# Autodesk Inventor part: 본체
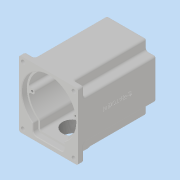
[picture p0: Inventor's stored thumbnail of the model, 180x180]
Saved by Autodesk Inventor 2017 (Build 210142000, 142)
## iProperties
Part Number: 본체
Material: 일반
Document SubType Name: Modeling
Designer: MRC
Density: 1 g/cm^3
Appearance: 기본값
Mass: 520.076 g
Surface Area: 1170.75 cm^2
Volume: 520.076 cm^3
Author: MRC
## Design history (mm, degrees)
sketch "스케치1"
  geometry: L1 (49, 55)-(-49, 55); L2 (-49, 55)-(-49, -55); L3 (-49, -55)-(49, -55); L4 (49, -55)-(49, 55); L5 (49, 55)-(-49, -55); L6 (-49, 55)-(49, -55); 1 further point
  constraints: 12 end point, 2 midpoint, 2 parallel, 1 horizontal, 1 perpendicular
  dimensions: "d0" = 98 distance of L3.end L2.end; "d1" = 110 distance of L2.end L1.end
extrude "돌출1" new body sketch "스케치1" distance "d2" = 10; taper "d3" = 0 deg
fillet "모깎기1" dims "d4" = 3
sketch "스케치2"
  geometry: L1 (46, 55)-(-46, 55) reference; L2 (33, -55)-(-33, -55); L3 (-33, -55)-(-33, 55); L4 (-33, 55)-(33, 55); L5 (33, 55)-(33, -55); L6 (33, -55)-(-33, 55); L7 (-33, -55)-(33, 55); 1 further point
  constraints: 12 end point, 2 midpoint, 2 parallel, 1 horizontal, 1 perpendicular, 1 point on line
  dimensions: "d5" = 66 distance of L3.end L4.end
extrude "돌출2" join sketch "스케치2" distance "d6" = 120; taper "d7" = 0 deg
sketch "스케치3"
  geometry: L1 (-49, -38)-(49, -38); L2 (49, -38)-(49, 28); L3 (49, 28)-(-49, 28); L4 (-49, 28)-(-49, -38); L5 (-49, -38)-(49, 28); L6 (49, -38)-(-49, 28); L7 (46, 55)-(-46, 55) reference; 3 further points
  constraints: 12 end point, 3 midpoint, 2 parallel, 1 horizontal, 1 perpendicular, 1 vertical alignment
  dimensions: "d8" = 98 distance of L3.end L2.end; "d9" = 66 distance of L2.end L1.end; "d10" = 27 distance between parallel lines of L7 L3
extrude "돌출3" join sketch "스케치3" distance "d11" = 120; taper "d12" = 0 deg
fillet "모깎기2" dims "d13" = 3
fillet "모깎기3" dims "d14" = 3
fillet "모깎기4" dims "d15" = 3
fillet "모깎기5" dims "d16" = 3
sketch "스케치4"
  geometry: L1 (-49, -41)-(-49, -52) reference; L2 (-46, -55)-(-36, -55) reference; C1 r 3.5 at (-42, -48); C2 r 3.5 at (-42, 48); C3 r 3.5 at (42, 48); C4 r 3.5 at (42, -48); 1 further point
  constraints: 4 centre point, 2 horizontal alignment, 2 vertical alignment
  dimensions: "d17" = 7 diameter of C1; "d18" = 7 diameter of C2; "d19" = 7 diameter of C3; "d20" = 7 diameter of C4; "d21" = 7 distance from line of L1 C1.centre; "d22" = 7 distance from line of L2 C1.centre; "d23" = 84 distance of C4.centre C1.centre; "d24" = 96 distance of C1.centre C2.centre
extrude "돌출4" cut sketch "스케치4" distance "d25" = 120; taper "d26" = 0 deg
sketch "스케치5"
  geometry: L1 (-27, -21)-(27, -21); L2 (27, -21)-(27, 33); L3 (27, 33)-(-27, 33); L4 (-27, 33)-(-27, -21); L5 (-27, -21)-(27, 33); L6 (27, -21)-(-27, 33); L7 (-30, -55)-(30, -55) reference; 3 further points
  constraints: 12 end point, 3 midpoint, 2 parallel, 1 horizontal, 1 perpendicular, 1 vertical alignment
  dimensions: "d27" = 54 distance of L3.end L2.end; "d28" = 54 distance of L2.end L1.end; "d29" = 61 distance from line of L7 point (0, 6)
extrude "돌출5" join sketch "스케치5" distance "d30" = 7; taper "d31" = 0 deg
fillet "모깎기6" dims "d32" = 3
fillet "모깎기7" dims "d33" = 3
sketch "스케치6"
  geometry: L1 (-46, 55)-(46, 55) reference; L2 (-23, -33.249)-(-23, -42); L3 (-20, -45)-(20, -45); L4 (23, -42)-(23, -33.249); L5 (0, 0)-(0, -65.918); A1 r 42 centre (0, 5) between (25.375, -28.468) and (-25.375, -28.468); A2 r 6 centre (29, -33.249) between (25.375, -28.468) and (23, -33.249); A3 r 6 centre (-29, -33.249) between (-23, -33.249) and (-25.375, -28.468); A4 r 3 centre (20, -42) between (20, -45) and (23, -42); A5 r 3 centre (-20, -42) between (-23, -42) and (-20, -45); 4 further points
  constraints: 12 point on circle, 8 end point, 8 tangent, 6 point on line, 5 centre point, 2 equal radius, 2 perpendicular, 2 vertical, 1 vertical alignment, 1 other
  dimensions: "d34" = 84 diameter of A1; "d35" = 50 distance from line of L1 A1.centre; "d36" = 46 distance of point (-23, -45) point (23, -45); "d37" = 50 distance from line of A1.centre L3; "d38" = 6 radius of A2; "d39" = 3 radius of A4
extrude "돌출6" cut sketch "스케치6" distance "d40" = 121; taper "d41" = 0 deg
sketch "스케치7"
  geometry: L1 (-23, -42)-(-23, -33.249) reference; L2 (20, -45)-(-20, -45) reference; L3 (23, -33.249)-(23, -42) reference; L4 (-26, -42)-(-26, -33.249); L5 (26, -33.249)-(26, -42); L6 (20, -48)-(-20, -48); A1 r 6 centre (29, -33.249) between (25.375, -28.468) and (23, -33.249) reference; A2 r 42 centre (0, 5) between (25.375, -28.468) and (-25.375, -28.468) reference; A3 r 6 centre (-29, -33.249) between (-23, -33.249) and (-25.375, -28.468) reference; A4 r 3 centre (-20, -42) between (-23, -42) and (-20, -45) reference; A5 r 3 centre (20, -42) between (20, -45) and (23, -42) reference; A6 r 6 centre (-20, -42) between (-26, -42) and (-20, -48); A7 r 3 centre (-29, -33.249) between (-26, -33.249) and (-27.188, -30.859); A8 r 45 centre (0, 5) between (27.188, -30.859) and (-27.188, -30.859); A9 r 3 centre (29, -33.249) between (27.188, -30.859) and (26, -33.249); A10 r 6 centre (20, -42) between (20, -48) and (26, -42); 1 further point
  constraints: 10 point on circle, 6 end point, 5 centre point, 7 other
  dimensions: "d42" = 3 distance between parallel lines of L2 L6
extrude "돌출7" cut sketch "스케치7" distance "d43" = 9; taper "d44" = 0 deg
chamfer "모따기1" distance "d45" = 1; stored, may be unused: second distance "d46" = 2, angle "d47" = 45 deg
sketch "스케치8"
  geometry: L1 (-46, 55)-(46, 55) reference; L2 (35.778, 1.006)-(41.81, 1.006); L3 (35.778, 8.994)-(41.81, 8.994); A1 r 36 centre (0, 5) between (36, 5) and (35.778, 1.006); A2 r 42 centre (0, 5) between (25.375, -28.468) and (-25.375, -28.468) reference; A3 r 4 centre (36, 5) between (36.222, 8.994) and (36.222, 1.006); 1 further point
  constraints: 9 point on circle, 4 end point, 2 centre point, 2 horizontal, 2 point on line, 1 horizontal alignment, 1 vertical alignment
  dimensions: "d48" = 72 diameter of A1; "d49" = 50 distance from line of L1 A1.centre; "d50" = 8 diameter of A3
extrude "돌출8" join sketch "스케치8" distance "d51" = 112; taper "d52" = 0 deg
fillet "모깎기8" dims "d53" = 3
fillet "모깎기9" dims "d54" = 3
sketch "스케치9"
  geometry: A1 r 4 centre (36, 5) between (35.778, 8.994) and (35.778, 1.006) reference; 2 further points
  constraints: 1 coincident
hole "구멍1" sketch "스케치9" at (36, 5) diameter "d55" = 3.242; stored, may be unused: countersink angle "d59" = 90 deg, drill point angle "d61" = 118 deg; dims "d56" = 7, "d57" = 4, "d58" = 2, "d60" = 9
sketch "스케치10"
  geometry: L1 (-46, 55)-(46, 55) reference; A1 r 21 centre (0, -6) between (-12.163, 11.119) and (12.163, 11.119); A2 r 15 centre (0, 25) between (11.584, 15.47) and (-11.584, 15.47); A3 r 3 centre (13.901, 13.565) between (11.584, 15.47) and (12.163, 11.119); A4 r 3 centre (-13.901, 13.565) between (-12.163, 11.119) and (-11.584, 15.47); 1 further point
  constraints: 8 point on circle, 4 centre point, 4 tangent, 2 vertical alignment, 1 equal radius
  dimensions: "d62" = 42 diameter of A1; "d63" = 61 distance from line of L1 A1.centre; "d64" = 30 diameter of A2; "d65" = 30 distance from line of L1 A2.centre; "d66" = 3 radius of A3 (derived)
extrude "돌출9" join sketch "스케치10" distance "d67" = 7; taper "d68" = 0 deg
fillet "모깎기10" dims "d69" = 3
sketch "스케치11"
  geometry: C1 r 17.5 at (0, -6); A1 r 21 centre (0, -6) between (-12.163, 11.119) and (12.163, 11.119) reference; 1 further point
  constraints: 1 centre point, 1 coincident
  dimensions: "d70" = 35 diameter of C1
extrude "돌출10" cut sketch "스케치11" distance "d71" = 10; taper "d72" = 0 deg
sketch "스케치12"
  geometry: A1 r 15 centre (0, 25) between (11.584, 15.47) and (-11.584, 15.47) reference; 2 further points
  constraints: 1 coincident
hole "구멍2" sketch "스케치12" at (0, 25) diameter "d73" = 19; stored, may be unused: countersink angle "d77" = 90 deg, drill point angle "d79" = 0 deg; dims "d74" = 7, "d75" = 22, "d76" = 7, "d78" = 10
fillet "모깎기11" dims "d80" = 3
fillet "모깎기12" dims "d81" = 0.3
chamfer "모따기2" distance "d82" = 1; stored, may be unused: second distance "d83" = 2, angle "d84" = 45 deg
sketch "스케치13"
  geometry: L1 (-27, 30)-(-27, -18) reference; L2 (24, 33)-(-24, 33) reference; C1 r 14 at (0, 6); 3 further points
  constraints: 2 midpoint, 1 centre point, 1 horizontal alignment, 1 vertical alignment
  dimensions: "d85" = 28 diameter of C1
extrude "돌출11" cut sketch "스케치13" stored distance "d86" = 10; taper "d87" = 0 deg
sketch "스케치14"
  geometry: C1 r 14 at (0, 6) reference; C2 r 16 at (0, 6); 1 further point
  constraints: 1 centre point, 1 coincident
  dimensions: "d88" = 32 diameter of C2
extrude "돌출12" cut sketch "스케치14" distance "d89" = 8.3; taper "d90" = 0 deg
fillet "모깎기13" dims "d91" = 0.3
chamfer "모따기3" distance "d92" = 0.8; stored, may be unused: second distance "d93" = 2, angle "d94" = 30 deg
sketch "스케치15"
  geometry: L1 (0, 0)-(92, 0) reference; C1 r 15 at (46, 89); 2 further points
  constraints: 1 centre point, 1 midpoint, 1 vertical alignment
  dimensions: "d95" = 30 diameter of C1; "d96" = 89 distance from line of L1 C1.centre
extrude "돌출13" join sketch "스케치15" distance "d97" = 5; taper "d98" = 0 deg
sketch "스케치16"
  geometry: L1 (0, 0)-(92, 0) reference; C1 r 22.5 at (46, 40); 2 further points
  constraints: 1 centre point, 1 midpoint, 1 vertical alignment
  dimensions: "d99" = 45 diameter of C1; "d100" = 40 distance from line of L1 C1.centre
extrude "돌출14" join sketch "스케치16" distance "d101" = 10; taper "d102" = 0 deg
fillet "모깎기14" dims "d103" = 3
sketch "스케치18"
  geometry: C1 r 15 at (20, 80) reference; C2 r 15 at (20, 80); 1 further point
  constraints: 1 centre point, 1 coincident
  dimensions: "d104" = 30 diameter of C2
extrude "돌출15" cut sketch "스케치18" distance "d105" = 5; taper "d106" = 0 deg
chamfer "모따기4" distance "d107" = 1; stored, may be unused: second distance "d108" = 2, angle "d109" = 30 deg
chamfer "모따기5" distance "d124" = 1; stored, may be unused: second distance "d125" = 2, angle "d126" = 45 deg
sketch "스케치20"
  geometry: C1 r 15 at (0, 0) reference; C2 r 10 at (0, 0); 1 further point
  constraints: 1 centre point, 1 coincident
  dimensions: "d110" = 20 diameter of C2
extrude "돌출16" cut sketch "스케치20" stored distance "d111" = 5; taper "d112" = 0 deg
sketch "스케치21"
  geometry: C1 r 22.5 at (0, 0) reference; 2 further points
  constraints: 1 coincident
hole "구멍3" sketch "스케치21" at (0, 0) diameter "d113" = 33.376; stored, may be unused: countersink angle "d117" = 90 deg, drill point angle "d119" = 0 deg; dims "d114" = 70, "d115" = 32, "d116" = 7, "d118" = 77.3
sketch "스케치22"
  geometry: L1 (104, 130)-(83, 130) reference; L2 (80, 13)-(80, 127) reference; 2 further points
  constraints: 1 other
  dimensions: "d120" = 65 distance from line of L1 point (47, 65); "d121" = 33 distance from line of L2 point (47, 65)
feature "엠보싱1" sketch "스케치22" dims "d5" = 66, "d122" = 0.5, "d123" = 0
node "솔리드1"
mirror "미러1"
mirror "미러2"
node "투영된 루프1"
